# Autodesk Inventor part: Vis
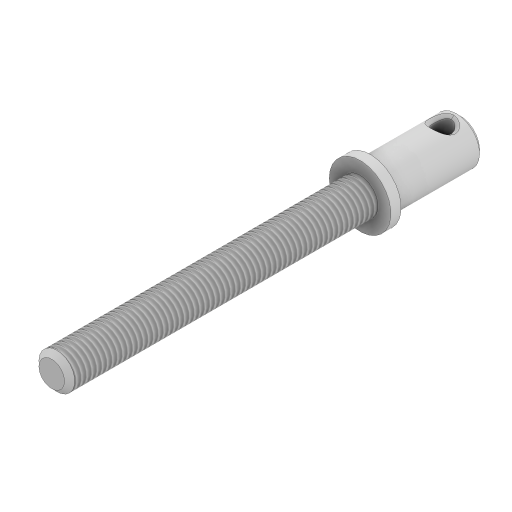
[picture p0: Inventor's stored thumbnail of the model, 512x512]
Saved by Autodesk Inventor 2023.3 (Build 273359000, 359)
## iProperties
Created: 2024-11
Part Number: Vis
Material: Générique
Description: STEP AP203
Document SubType Name: Modeling
Designer: Thier
Density: 1 g/cm^3
Appearance: Par défaut
Title: Vis.STEP
Revision Number: ANY
Sending System: SolidWorks 2017
Preprocessor: SwSTEP 2.0
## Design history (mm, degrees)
feature "Chanfrein3"
feature "Filetage1" dims "d0" = 118, "d1" = 0
node "Solide1"
